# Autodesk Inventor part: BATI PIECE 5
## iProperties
Created: 2004-11
Part Number: BATI PIECE 5
Document SubType Name: Modeling
Designer: Bruno
Manufacturer: Standard
Standards Organization: Custom
Author: Bruno
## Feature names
1. Base1
